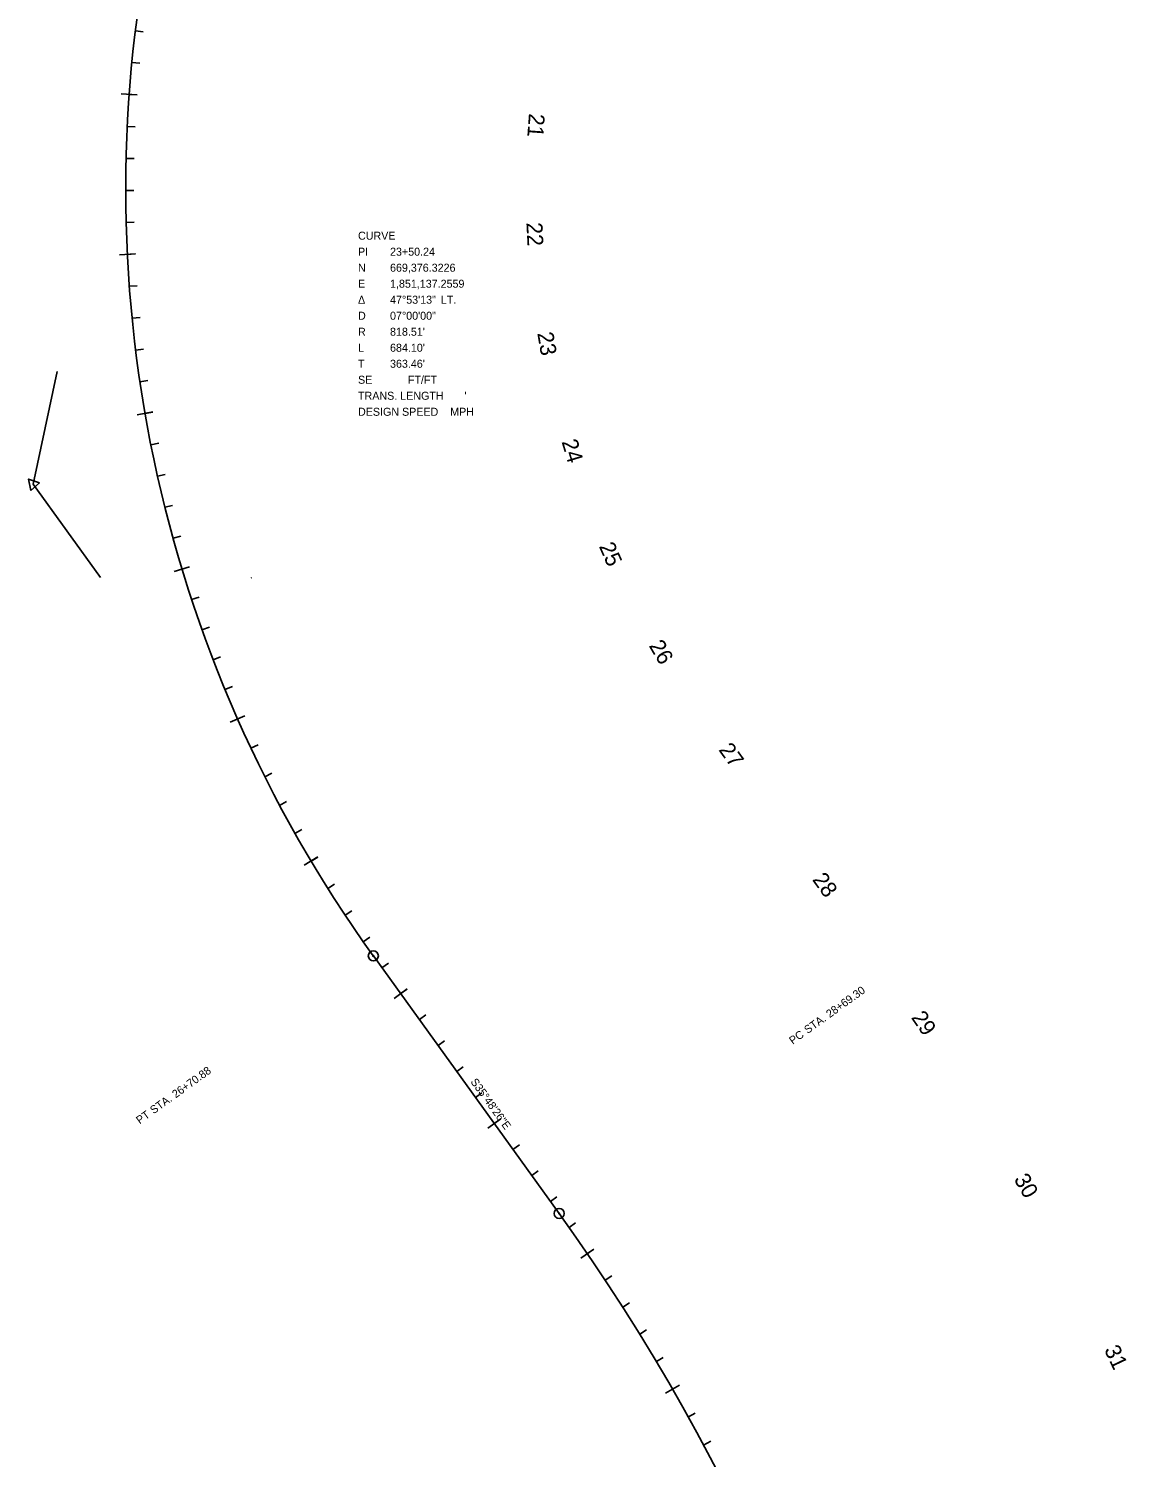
# Model space of a CAD drawing. Extents: x 1849564 to 1851966, y 666816 to 670715.
# Drawn here: x 1851134 to 1851820, y 668768 to 669661 of the extents above; entities that cross this region are included whole.
import ezdxf

# ---------------------------------------------------------------- set-up
doc = ezdxf.new("R2010")
doc.units = 0
for name, color, linetype in [('CONCEPT - PAVEMENT MARKING - Crosswalk Long', 7, 'Continuous'), ('CONCEPT - PAVEMENT MARKING - Crosswalk Parallel', 7, 'Continuous'), ('CONCEPT - PAVEMENT MARKING - Stop Bar', 7, 'Continuous'), ('CONCEPT - PAVEMENT MARKING - Striping - Yellow', 7, 'Continuous'), ('Default', 7, 'Continuous'), ('DES - DRG - Special Ditches', 7, 'Continuous'), ('DES - MODEL - Lines - Barrier', 7, 'Continuous')]:
    doc.layers.add(name, color=color, linetype=linetype)

msp = doc.modelspace()

# ---------------------------------------------------------------- linework, layer by layer
at = {"layer": 'CONCEPT - PAVEMENT MARKING - Crosswalk Parallel'}
for q in [(1851152.32, 669446.73), (1851137.26, 669376.32), (1851179.38, 669317.93)]:
    msp.add_line((1851137.26, 669376.32), q, dxfattribs=at)
msp.add_lwpolyline([(1851141.32, 669377.18), (1851134.48, 669379.42), (1851135.96, 669372.37)], close=True, dxfattribs=at)
at = {"layer": 'CONCEPT - PAVEMENT MARKING - Stop Bar'}
for p, q in [((1851201.22, 669659.55), (1851206.16, 669658.94)), ((1851199.04, 669639.67), (1851203.99, 669639.18)), ((1851202.33, 669619.38), (1851192.36, 669620.1)), ((1851196.14, 669599.78), (1851201.11, 669599.54)), ((1851195.42, 669579.79), (1851200.4, 669579.67)), ((1851195.19, 669559.79), (1851200.17, 669559.79)), ((1851195.45, 669539.79), (1851200.43, 669539.92)), ((1851201.2, 669520.06), (1851191.21, 669519.56)), ((1851197.44, 669499.85), (1851202.41, 669500.21)), ((1851199.16, 669479.92), (1851204.12, 669480.41)), ((1851201.37, 669460.04), (1851206.32, 669460.65)), ((1851204.07, 669440.23), (1851208.99, 669440.96)), ((1851212.17, 669421.34), (1851202.32, 669419.63)), ((1851210.91, 669400.82), (1851215.79, 669401.79)), ((1851215.05, 669381.25), (1851219.91, 669382.34)), ((1851219.66, 669361.79), (1851224.49, 669363)), ((1851224.75, 669342.45), (1851229.55, 669343.78)), ((1851235.1, 669324.69), (1851225.53, 669321.79)), ((1851236.34, 669304.17), (1851241.07, 669305.73)), ((1851242.84, 669285.26), (1851247.53, 669286.93)), ((1851249.79, 669266.51), (1851254.44, 669268.29)), ((1851257.2, 669247.93), (1851261.8, 669249.83)), ((1851269.63, 669231.56), (1851260.49, 669227.52)), ((1851273.37, 669211.35), (1851277.87, 669213.47)), ((1851282.12, 669193.36), (1851286.57, 669195.6)), ((1851291.31, 669175.6), (1851295.7, 669177.94)), ((1851300.93, 669158.06), (1851305.26, 669160.51)), ((1851315.26, 669143.33), (1851306.68, 669138.21)), ((1851321.43, 669123.73), (1851325.64, 669126.38)), ((1851332.31, 669106.94), (1851336.45, 669109.7)), ((1851343.59, 669090.43), (1851347.67, 669093.29)), ((1851355.23, 669074.17), (1851359.27, 669077.08)), ((1851370.99, 669060.87), (1851362.88, 669055.02)), ((1851378.64, 669041.73), (1851382.68, 669044.64)), ((1851390.34, 669025.51), (1851394.38, 669028.42)), ((1851402.04, 669009.29), (1851406.08, 669012.2)), ((1851413.74, 668993.07), (1851417.78, 668995.98)), ((1851429.5, 668979.77), (1851421.39, 668973.92)), ((1851437.14, 668960.63), (1851441.18, 668963.54)), ((1851448.84, 668944.41), (1851452.88, 668947.32)), ((1851460.55, 668928.19), (1851464.58, 668931.1)), ((1851472.21, 668911.94), (1851476.27, 668914.82)), ((1851487.77, 668898.36), (1851479.52, 668892.71)), ((1851494.82, 668878.95), (1851498.97, 668881.7)), ((1851505.74, 668862.19), (1851509.93, 668864.88)), ((1851516.39, 668845.26), (1851520.62, 668847.88)), ((1851526.77, 668828.17), (1851531.05, 668830.72)), ((1851541.22, 668813.41), (1851532.55, 668808.42)), ((1851546.72, 668793.5), (1851551.08, 668795.92)), ((1851556.29, 668775.94), (1851560.68, 668778.29))]:
    msp.add_line(p, q, dxfattribs=at)
at = {"layer": 'CONCEPT - PAVEMENT MARKING - Striping - Yellow'}
for p, q in [((1851197.34, 669619.74), (1851202.31, 669619.38)), ((1851196.2, 669519.81), (1851201.18, 669520.05)), ((1851207.25, 669420.48), (1851212.15, 669421.33)), ((1851230.32, 669323.24), (1851235.08, 669324.69)), ((1851269.63, 669231.56), (1851260.47, 669227.51)), ((1851310.97, 669140.77), (1851315.24, 669143.32)), ((1851366.94, 669057.95), (1851370.97, 669060.86)), ((1851425.44, 668976.85), (1851429.48, 668979.76)), ((1851483.65, 668895.53), (1851487.75, 668898.35)), ((1851541.22, 668813.41), (1851532.53, 668808.41))]:
    msp.add_line(p, q, dxfattribs=at)
for centre, radius in [((1851349.9, 669081.56), 3.14), ((1851349.9, 669081.56), 0.33), ((1851465.98, 668920.65), 3.14), ((1851465.98, 668920.65), 0.33)]:
    msp.add_circle(centre, radius, dxfattribs=at)
at = {"layer": 'Default'}
msp.add_line((1851349.9, 669081.56), (1851465.98, 668920.65), dxfattribs=at)
for centre, radius, start, end in [((1852013.7, 669560.44), 818.51, 167.92032, 215.80713), ((1850433.4, 668175.73), 1273.24, 344.58842, 35.80713)]:
    msp.add_arc(centre, radius, start, end, dxfattribs=at)
at = {"layer": 'DES - DRG - Special Ditches'}
msp.add_line((1851349.9, 669081.56), (1851465.98, 668920.65), dxfattribs=at)
for centre, radius, start, end in [((1852013.7, 669560.44), 818.51, 167.92032, 215.80713), ((1850433.4, 668175.73), 1273.24, 344.58842, 35.80713)]:
    msp.add_arc(centre, radius, start, end, dxfattribs=at)
at = {"layer": 'DES - MODEL - Lines - Barrier'}
msp.add_circle((1851273.66, 669317.78), 0.05, dxfattribs=at)

# ---------------------------------------------------------------- texts
at = {"layer": 'CONCEPT - PAVEMENT MARKING - Crosswalk Long'}
for s, p in [('CURVE    ', (1851340.33, 669528.98)), ('PI', (1851340.33, 669518.98)), ('23+50.24', (1851360.33, 669518.98)), ('N', (1851340.33, 669508.98)), ('669,376.3226', (1851360.33, 669508.98)), ('E', (1851340.33, 669498.98)), ('1,851,137.2559', (1851360.33, 669498.98)), ('Δ', (1851340.33, 669488.98)), ('47°53\'13"', (1851360.33, 669488.98)), (' LT.', (1851390.23, 669488.98)), ('D', (1851340.33, 669478.98)), ('07°00\'00"', (1851360.33, 669478.98)), ('R', (1851340.33, 669468.98)), ("818.51'", (1851360.33, 669468.98)), ('L', (1851340.33, 669458.98)), ("684.10'", (1851360.33, 669458.98)), ('T', (1851340.33, 669448.98)), ("363.46'", (1851360.33, 669448.98)), ('SE', (1851340.33, 669438.98)), ('      FT/FT', (1851360.33, 669438.98)), ("TRANS. LENGTH       '", (1851340.33, 669428.98)), ('DESIGN SPEED    MPH', (1851340.33, 669418.98))]:
    msp.add_text(s, height=5, dxfattribs=at).set_placement(p)
for s, p in [('28+69.30', (1851635.06, 669042.62)), (' STA. ', (1851619.8, 669031.62)), ('PC', (1851611.96, 669025.96)), ('26+70.88', (1851226.39, 668992.46)), (' STA. ', (1851211.13, 668981.46)), ('PT', (1851203.92, 668976.25))]:
    msp.add_text(s, height=4.98, rotation=35.80713, dxfattribs=at).set_placement(p)
at = {"layer": 'CONCEPT - PAVEMENT MARKING - Crosswalk Parallel'}
msp.add_text('S35°48\'26"E', height=4.98, rotation=305.80713, dxfattribs=at).set_placement((1851410.37, 669002.86))
at = {"layer": 'CONCEPT - PAVEMENT MARKING - Stop Bar'}
for s, rotation, p in [('21', 265.84544, (1851447.16, 669608.07)), ('22', 272.84545, (1851445.53, 669539.58)), ('23', 279.84546, (1851452.3, 669470.54)), ('24', 286.84547, (1851467.44, 669402.77)), ('25', 293.84548, (1851490.71, 669337.43)), ('26', 300.84549, (1851521.8, 669275.32)), ('27', 305.80713, (1851565.34, 669210.23)), ('28', 305.80713, (1851623.84, 669129.14)), ('29', 304.42543, (1851685.66, 669043)), ('30', 299.92543, (1851749.86, 668942.05)), ('31', 295.42544, (1851806.33, 668835.54))]:
    msp.add_text(s, height=9.96, rotation=rotation, dxfattribs=at).set_placement(p)
at = {"layer": 'CONCEPT - PAVEMENT MARKING - Striping - Yellow'}
for s, rotation, p in [('25', 293.84548, (1851490.71, 669337.43)), ('30', 299.92543, (1851749.86, 668942.05))]:
    msp.add_text(s, height=9.96, rotation=rotation, dxfattribs=at).set_placement(p)

doc.saveas('drawing.dxf')
